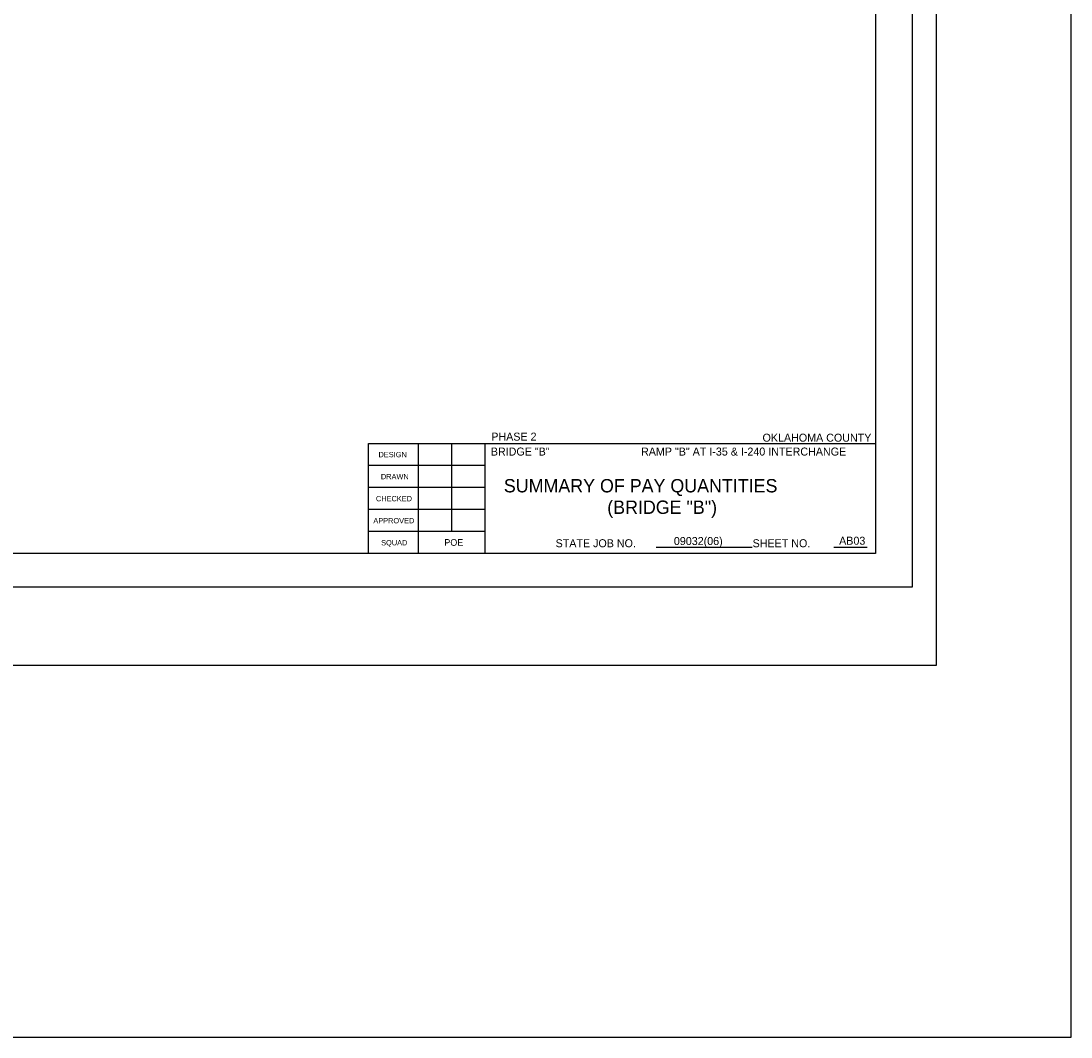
# Model space of a CAD drawing. Extents: x 12310.9 to 12354.4, y 579 to 640.5.
# Drawn here: x 12338.64 to 12354.38, y 579.03 to 594.26 of the extents above; entities that cross this region are included whole.
import ezdxf

# ---------------------------------------------------------------- set-up
doc = ezdxf.new("R2010")
doc.units = 0
for name, color, linetype in [('S', 7, 'Continuous'), ('SHT_Plot_Shape_Full', 7, 'Continuous'), ('SHT_Plot_Shape_Half', 7, 'Continuous'), ('SHT_Sheet_Border', 7, 'Continuous'), ('SHT_Standard_Sheet_Lines', 7, 'Continuous'), ('SHT_Standard_Sheet_Txt', 7, 'Continuous'), ('T', 7, 'Continuous'), ('T-Title', 7, 'Continuous')]:
    doc.layers.add(name, color=color, linetype=linetype)

msp = doc.modelspace()

# ---------------------------------------------------------------- linework, layer by layer
at = {"layer": 'S'}
msp.add_lwpolyline([(12354.38, 640.488), (12310.944, 640.488), (12310.944, 579.031), (12354.38, 579.031)], close=True, dxfattribs=at)
at = {"layer": 'SHT_Plot_Shape_Full'}
msp.add_lwpolyline([(12316.36, 608.6), (12352.36, 608.6), (12352.36, 584.6), (12316.36, 584.6)], close=True, dxfattribs=at)
at = {"layer": 'SHT_Plot_Shape_Half'}
msp.add_lwpolyline([(12317.998, 607.775), (12351.998, 607.775), (12351.998, 585.775), (12317.998, 585.775)], close=True, dxfattribs=at)
at = {"layer": 'SHT_Sheet_Border'}
for p, q in [((12343.848, 586.275), (12343.848, 587.925)), ((12343.848, 587.925), (12351.448, 587.925)), ((12345.598, 586.275), (12345.598, 587.926))]:
    msp.add_line(p, q, dxfattribs=at)
msp.add_lwpolyline([(12351.448, 586.275), (12319.948, 586.275), (12319.948, 607.275), (12351.448, 607.275)], close=True, dxfattribs=at)
at = {"layer": 'SHT_Standard_Sheet_Lines'}
for p, q in [((12344.598, 586.275), (12344.598, 587.926)), ((12345.098, 586.605), (12345.098, 587.926)), ((12348.159, 586.371), (12349.599, 586.371)), ((12350.823, 586.371), (12351.326, 586.371))]:
    msp.add_line(p, q, dxfattribs=at)
for points in [[(12345.598, 587.595), (12343.848, 587.595)], [(12345.598, 587.265), (12343.848, 587.265)], [(12345.598, 586.935), (12343.848, 586.935)], [(12345.598, 586.605), (12343.848, 586.605)]]:
    msp.add_lwpolyline(points, dxfattribs=at)

# ---------------------------------------------------------------- texts
at = {"layer": 'SHT_Standard_Sheet_Txt'}
for s, height, p in [('DESIGN', 0.08, (12344, 587.72)), ('DRAWN', 0.08, (12344.035, 587.39)), ('CHECKED', 0.08, (12343.961, 587.06)), ('APPROVED', 0.08, (12343.922, 586.729)), ('SQUAD', 0.08, (12344.039, 586.399)), ('STATE JOB NO.', 0.12, (12346.654, 586.371)), ('SHEET NO. ', 0.12, (12349.607, 586.371))]:
    msp.add_text(s, height=height, dxfattribs=at).set_placement(p)
at = {"layer": 'T'}
for s, height, p in [('PHASE 2', 0.12, (12345.69, 587.969)), ('OKLAHOMA COUNTY', 0.12, (12349.756, 587.953)), ('BRIDGE "B"', 0.12, (12345.683, 587.745)), ('RAMP "B" AT I-35 & I-240 INTERCHANGE', 0.12, (12347.935, 587.745)), ('POE', 0.1, (12344.987, 586.393)), ('09032(06)', 0.12, (12348.427, 586.404)), ('AB03', 0.12, (12350.904, 586.409))]:
    msp.add_text(s, height=height, dxfattribs=at).set_placement(p)
at = {"layer": 'T-Title'}
for s, p in [('SUMMARY OF PAY QUANTITIES', (12345.878, 587.193)), ('(BRIDGE "B")', (12347.428, 586.871))]:
    msp.add_text(s, height=0.2, dxfattribs=at).set_placement(p)

doc.saveas('drawing.dxf')
